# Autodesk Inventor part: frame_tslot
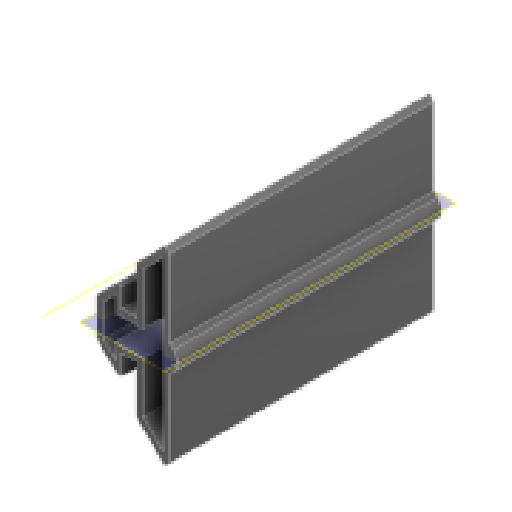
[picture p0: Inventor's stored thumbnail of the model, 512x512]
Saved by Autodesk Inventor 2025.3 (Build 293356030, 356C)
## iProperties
Created: 2026-03
Part Number: frame_tslot
Material: Plastica ABS
Document SubType Name: Modeling
Designer: R5800u
Density: 1.06 g/cm^3
Appearance: Liscia - Nero
Author: R5800u
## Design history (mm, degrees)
sketch "Schizzo1"
  geometry: L1 (7.61, 290.16)-(7.91, 289.64) reference; L2 (7.91, 289.64)-(7.61, 289.121) reference; L3 (7.61, 289.121)-(7.61, 286.701) reference; L4 (7.61, 286.701)-(4.549, 283.64) reference; L5 (4.549, 283.64)-(3.61, 283.64) reference; L6 (3.61, 283.64)-(3.61, 286.64) reference; L7 (3.61, 286.64)-(1.91, 286.64) reference; L8 (1.61, 286.34)-(1.61, 280.64) reference; L9 (2.61, 279.64)-(8.31, 279.64) reference; L10 (8.61, 279.94)-(8.61, 281.64) reference; L11 (8.61, 281.64)-(5.61, 281.64) reference; L12 (5.61, 281.64)-(5.61, 282.58) reference; L13 (5.61, 282.58)-(8.67, 285.64) reference; L14 (8.67, 285.64)-(11.09, 285.64) reference; L15 (11.09, 285.64)-(11.61, 285.94) reference; L16 (11.61, 285.94)-(12.129, 285.64) reference; L17 (12.129, 285.64)-(14.549, 285.64) reference; L18 (14.549, 285.64)-(17.61, 282.58) reference; L19 (17.61, 282.58)-(17.61, 281.64) reference; L20 (17.61, 281.64)-(14.61, 281.64) reference; L21 (14.61, 281.64)-(14.61, 279.94) reference; L22 (14.91, 279.64)-(20.61, 279.64) reference; L23 (21.61, 280.64)-(21.61, 286.34) reference; L24 (21.31, 286.64)-(19.61, 286.64) reference; L25 (19.61, 286.64)-(19.61, 283.64) reference; L26 (19.61, 283.64)-(18.67, 283.64) reference; L27 (18.67, 283.64)-(15.61, 286.701) reference; L28 (15.61, 286.701)-(15.61, 289.121) reference; L29 (15.61, 289.121)-(15.31, 289.64) reference; L30 (15.31, 289.64)-(15.61, 290.16) reference; L31 (15.61, 290.16)-(15.61, 292.58) reference; L32 (15.61, 292.58)-(18.67, 295.64) reference; L33 (18.67, 295.64)-(19.61, 295.64) reference; L34 (19.61, 295.64)-(19.61, 292.64) reference; L35 (19.61, 292.64)-(21.31, 292.64) reference; L36 (21.61, 292.94)-(21.61, 298.64) reference; L37 (20.61, 299.64)-(14.91, 299.64) reference; L38 (14.61, 299.34)-(14.61, 297.64) reference; L39 (14.61, 297.64)-(17.61, 297.64) reference; L40 (17.61, 297.64)-(17.61, 296.701) reference; L41 (17.61, 296.701)-(14.549, 293.64) reference; L42 (14.549, 293.64)-(12.129, 293.64) reference; L43 (12.129, 293.64)-(11.61, 293.34) reference; L44 (11.61, 293.34)-(11.09, 293.64) reference; L45 (11.09, 293.64)-(8.67, 293.64) reference; L46 (8.67, 293.64)-(5.61, 296.701) reference; L47 (5.61, 296.701)-(5.61, 297.64) reference; L48 (5.61, 297.64)-(8.61, 297.64) reference; L49 (8.61, 297.64)-(8.61, 299.34) reference; L50 (8.31, 299.64)-(2.61, 299.64) reference; L51 (1.61, 298.64)-(1.61, 292.94) reference; L52 (1.91, 292.64)-(3.61, 292.64) reference; L53 (3.61, 292.64)-(3.61, 295.64) reference; L54 (3.61, 295.64)-(4.549, 295.64) reference; L55 (4.549, 295.64)-(7.61, 292.58) reference; L56 (7.61, 292.58)-(7.61, 290.16) reference; L57 (21.71, 298.64)-(21.71, 292.94); L58 (21.31, 292.54)-(19.51, 292.54); L59 (19.51, 292.54)-(19.51, 295.54); L60 (19.51, 295.54)-(18.712, 295.54); L61 (18.712, 295.54)-(15.71, 292.538); L62 (15.71, 292.538)-(15.71, 290.133); L63 (15.71, 289.148)-(15.71, 286.742); L64 (15.71, 286.742)-(18.712, 283.74)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; C1 r 2.1 at (11.61, 289.64) reference; A1 r 0.3 centre (1.91, 286.34) between (1.91, 286.64) and (1.61, 286.34) reference; A2 r 1 centre (2.61, 280.64) between (1.61, 280.64) and (2.61, 279.64) reference; A3 r 0.3 centre (8.31, 279.94) between (8.31, 279.64) and (8.61, 279.94) reference; A4 r 0.3 centre (14.91, 279.94) between (14.61, 279.94) and (14.91, 279.64) reference; A5 r 1 centre (20.61, 280.64) between (20.61, 279.64) and (21.61, 280.64) reference; A6 r 0.3 centre (21.31, 286.34) between (21.61, 286.34) and (21.31, 286.64) reference; A7 r 0.3 centre (21.31, 292.94) between (21.31, 292.64) and (21.61, 292.94) reference; A8 r 1 centre (20.61, 298.64) between (21.61, 298.64) and (20.61, 299.64) reference; A9 r 0.3 centre (14.91, 299.34) between (14.91, 299.64) and (14.61, 299.34) reference; A10 r 0.3 centre (8.31, 299.34) between (8.61, 299.34) and (8.31, 299.64) reference; A11 r 1 centre (2.61, 298.64) between (2.61, 299.64) and (1.61, 298.64) reference; A12 r 0.3 centre (1.91, 292.94) between (1.61, 292.94) and (1.91, 292.64) reference; A13 r 0.4 centre (21.31, 286.34) between (21.71, 286.34) and (21.31, 286.74); A14 r 1.1 centre (20.61, 280.64) between (20.61, 279.54) and (21.71, 280.64); A15 r 0.4 centre (14.91, 279.94) between (14.51, 279.94) and (14.91, 279.54); A16 r 0.4 centre (8.31, 279.94) between (8.31, 279.54) and (8.71, 279.94); A17 r 1.1 centre (2.61, 280.64) between (1.51, 280.64) and (2.61, 279.54); A18 r 0.4 centre (1.91, 286.34) between (1.91, 286.74) and (1.51, 286.34); A19 r 0.4 centre (1.91, 292.94) between (1.51, 292.94) and (1.91, 292.54); A20 r 1.1 centre (2.61, 298.64) between (2.61, 299.74) and (1.51, 298.64); A21 r 0.4 centre (8.31, 299.34) between (8.71, 299.34) and (8.31, 299.74); A22 r 0.4 centre (14.91, 299.34) between (14.91, 299.74) and (14.51, 299.34); A23 r 1.1 centre (20.61, 298.64) between (21.71, 298.64) and (20.61, 299.74); 2 further points
  constraints: 126 end point, 22 point on circle, 11 centre point, 4 point on line, 3 vertical, 2 horizontal, 2 perpendicular, 1 midpoint, 63 other
  dimensions: "d0" = 0.1 distance between parallel lines of L36 L57; "d10" = 11 distance between parallel lines of L62 L117
extrude "Estrusione1" new body sketch "Schizzo1" distance "d1" = 40; taper "d2" = 0 deg
mirror "Speculare1"
feature "Svuotamento1" dims "d3" = 1
node "Piano di lavoro1"
node "Asse di lavoro1"
sketch "Schizzo2"
  geometry: L1 (26.71, 304.74)-(26.71, 274.54) reference; L2 (26.71, 303.326)-(26.003, 304.033); L3 (21.71, 299.74)-(26.71, 304.74) reference; 1 further point
  constraints: 2 end point, 2 point on line, 1 perpendicular
  dimensions: "d9" = 1 distance from line of L1.start L2
extrude "Estrusione2" cut sketch "Schizzo2" extent not by distance; stored distance "d7" = 0; taper "d8" = 0 deg
mirror "Speculare2"
sketch "Schizzo3"
  geometry: L1 (26.71, 275.955)-(26.71, 303.326) reference; L2 (26.71, 289.64)-(28.71, 289.64); L3 (28.71, 289.64)-(26.71, 291.64); L4 (28.71, 289.64)-(26.71, 287.64); 2 further points
  constraints: 6 end point, 1 horizontal, 1 midpoint, 1 point on line, 1 symmetric about line
  dimensions: "d11" = 2 distance of L2.start L2.end; "d12" = 2 distance from line of L2 L3.end
extrude "Estrusione3" join sketch "Schizzo3" stored distance "d13" = 2 (= d11); taper "d14" = 0 deg
fillet "Raccordo1" dims "d15" = 2
node "Solido1"
node "Riferimento1"
